(* Logix 5000 project; controller ControlLogix 1756-L63 rev 16.7; software revision 16.03 *)

TASK MainTask (continuous, watchdog 500 ms) : MainProgram

MODULES
   Local : 1756-L63 (ICP 0, rev 16.7)
      MCM : vendor 1 type 0 code 15 (ICP 1, rev 1.1, Output RPI 5 ms)   // ProSoft Technology Modbus communication module for the Control logix platform
END_MODULES

TYPE _CmdControl :
STRUCT
   TriggerCmdCntrl : BOOL;
   NumberOfCommands : INT;
   PortNumber : INT;
   CommandIndex : INT[6];
   CmdsAddedToQueue : INT;
   CmdControlBlockID : INT;
   CmdCntrlPending : BOOL;
END_STRUCT
END_TYPE

TYPE _CoilArray :
STRUCT
   Boolean : BOOL[416];
END_STRUCT
END_TYPE

TYPE _EventCmd :
STRUCT
   EventCmdTrigger : BOOL;
   EventCmdPending : BOOL;
   PortNumber : INT;
   SlaveAddress : INT;
   InternalDBAddress : INT;
   PointCount : INT;
   SwapCode : INT;
   ModbusFunctionCode : INT;
   DeviceDBAddress : INT;
   EventCmdStatusReturned : INT;
   EventBlockID : INT;
END_STRUCT
END_TYPE

TYPE _Passthru :
STRUCT
   MBOffset : INT;
   MBOffsetBit : INT;
   MBMsgLen : INT;
   MBMsg : SINT[500];
   MBControl1 : CONTROL;
   MBControl2 : CONTROL;
   MBScratch : INT[3];
   MBCoil : _CoilArray;
END_STRUCT
END_TYPE

TYPE _SlavePollStatus :
STRUCT
   Port1Slave0Read : BOOL;
   Port1Slave128Read : BOOL;
   Port2Slave0Read : BOOL;
   Port2Slave128Read : BOOL;
   P1Slaves : INT[256];
   P2Slaves : INT[256];
END_STRUCT
END_TYPE

TYPE _Util :
STRUCT
   CmdControl : _CmdControl;
   EventCmd : _EventCmd;
   SlavePollStat : _SlavePollStatus;
   Passthru : _Passthru;
END_STRUCT
END_TYPE

TYPE MCMBlkStat :
STRUCT
   Read : INT;
   Write : INT;
   Parse : INT;
   Event : INT;
   Cmd : INT;
   Err : INT;
END_STRUCT
END_TYPE

TYPE MCMCmd :
STRUCT
   Enable : INT;
   IntAddress : INT;
   PollInt : INT;
   Count : INT;
   Swap : INT;
   Node : INT;
   Func : INT;
   DevAddress : INT;
END_STRUCT
END_TYPE

TYPE MCMCONFIG :
STRUCT
   ModDef : MCMModule;
   Port1 : MCMPort;
   Port2 : MCMPort;
   Port1MasterCmd : MCMCmd[100];
   Port2MasterCmd : MCMCmd[100];
END_STRUCT
END_TYPE

TYPE MCMCONTROL :
STRUCT
   WarmBoot : BOOL;
   ColdBoot : BOOL;
   BPLastRead : INT;
   BPLastWrite : INT;
   BlockIndex : INT;
   ReadDataSize : DINT;
   MaxReadBlock : DINT;
   WriteDataSize : DINT;
   MaxWriteBlock : DINT;
END_STRUCT
END_TYPE

TYPE MCMDATA :
STRUCT
   ReadData : INT[600];
   WriteData : INT[600];
END_STRUCT
END_TYPE

TYPE MCMModule :
STRUCT
   WriteStartReg : INT;
   WriteRegCnt : INT;
   ReadStartReg : INT;
   ReadRegCnt : INT;
   BPFail : INT;
   ErrStatPtr : INT;
END_STRUCT
END_TYPE

TYPE MCMModuleDef :
STRUCT
   CONFIG : MCMCONFIG;
   DATA : MCMDATA;
   STATUS : MCMSTATUS;
   CONTROL : MCMCONTROL;
   _UTIL : _Util;
END_STRUCT
END_TYPE

TYPE MCMPort :
STRUCT
   Enabled : INT;
   Type : INT;
   FloatFlag : INT;
   FloatStart : INT;
   FloatOffset : INT;
   Protocol : INT;
   Baudrate : INT;
   Parity : INT;
   DataBits : INT;
   StopBits : INT;
   RTSOn : INT;
   RTSOff : INT;
   MinResp : INT;
   UseCTS : INT;
   SlaveID : INT;
   BitInOffset : INT;
   WordInOffset : INT;
   OutOffset : INT;
   HoldOffset : INT;
   CmdCount : INT;
   MinCmdDelay : INT;
   CmdErrPtr : INT;
   RespTO : INT;
   RetryCount : INT;
   ErrorDelayCntr : INT;
   Reserved : INT;
   InterCharacterDelay : INT;
   Fcn99Offset : INT;
END_STRUCT
END_TYPE

TYPE MCMPortErrors :
STRUCT
   CmdReq : INT;
   CmdResp : INT;
   CmdErr : INT;
   Requests : INT;
   Responses : INT;
   ErrSent : INT;
   ErrRec : INT;
END_STRUCT
END_TYPE

TYPE MCMSTATUS :
STRUCT
   PassCnt : INT;
   Product : INT[2];
   Rev : INT[2];
   OP : INT[2];
   Run : INT[2];
   Prt1Errs : MCMPortErrors;
   Prt2Errs : MCMPortErrors;
   Blk : MCMBlkStat;
   Port1LastErr : INT;
   Port1PreviousErr : INT;
   Port2LastErr : INT;
   Port2PreviousErr : INT;
END_STRUCT
END_TYPE

ADD_ON_INSTRUCTION PSMCM   (* revision 2.2, ExecutePrescan *)
// Revision note:
// Added viewing capability for the Add_On Instruction
VAR_IN_OUT
   Local_C : SINT[400]; {required}
   Local_Input : INT[250]; {required}
   Local_Output : INT[248]; {required}
   MCM : MCMModuleDef; {required}
END_VAR
VAR
   MJFAULTS : DINT[12];
END_VAR

ROUTINE Logic   (* ladder *)
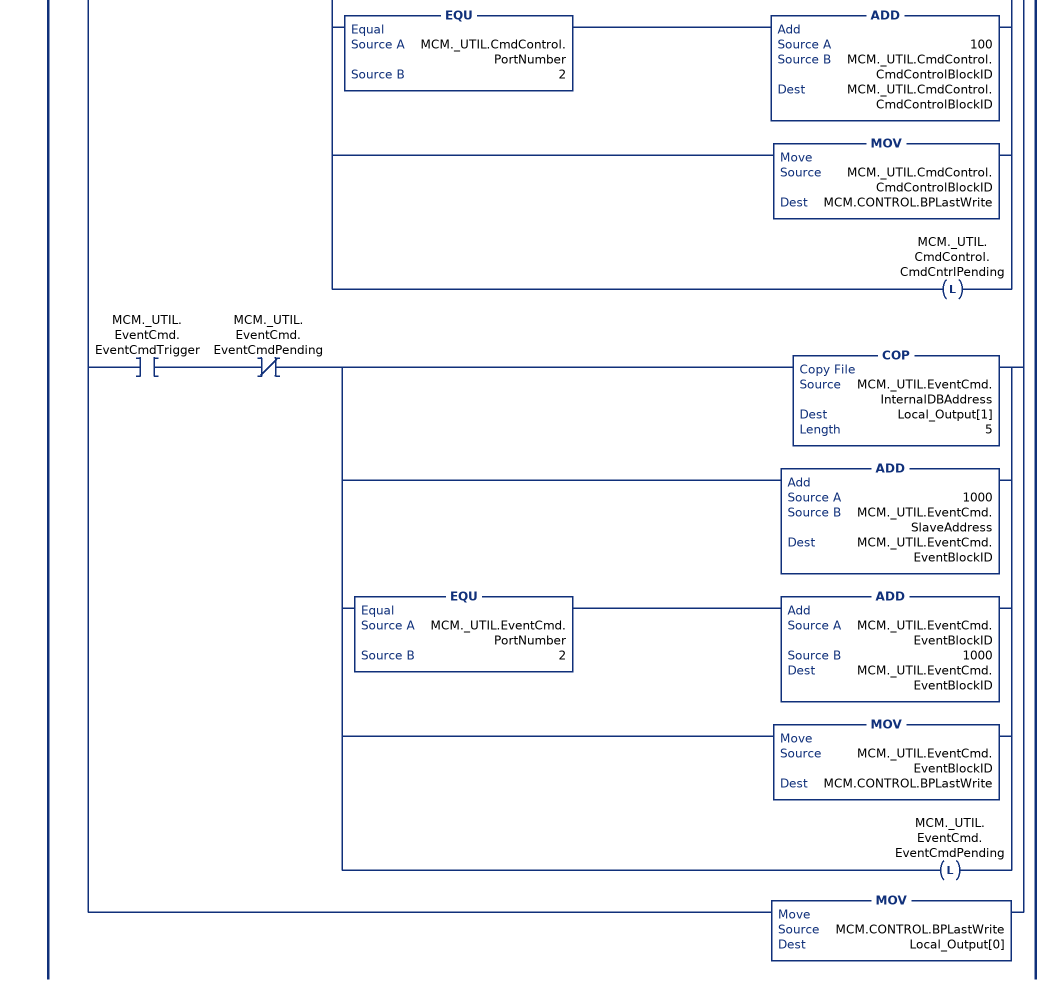
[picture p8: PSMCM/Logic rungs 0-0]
   0: NEQ(Local_Input[249],MCM.CONTROL.BPLastRead)[MOV(Local_Input[249],MCM.CONTROL.BPLastRead) ,[EQU(-1,MCM.CONTROL.BPLastRead) ,EQU(0,MCM.CONTROL.BPLastRead) ] [COP(Local_Input[202],MCM.STATUS.PassCnt,1) ,COP(Local_Input[203],MCM.STATUS.Product[0],8) ,COP(Local_Input[211],MCM.STATUS.Prt1Errs.CmdReq,7) ,COP(Local_Input[218],MCM.STATUS.Prt2Errs.CmdReq,7) ,COP(Local_Input[225],MCM.STATUS.Blk.Read,6) ,COP(Local_Input[231],MCM.STATUS.Port1LastErr,4) ] ,LIM(1,MCM.CONTROL.BPLastRead,MCM.CONTROL.MaxReadBlock) [CPT(MCM.CONTROL.BlockIndex,(MCM.CONTROL.BPLastRead-1)*200) ,COP(Local_Input[2],MCM.DATA.ReadData[MCM.CONTROL.BlockIndex],200) ,COP(Local_Input[202],MCM.STATUS.PassCnt,1) ,COP(Local_Input[203],MCM.STATUS.Product[0],8) ,COP(Local_Input[211],MCM.STATUS.Prt1Errs.CmdReq,7) ,COP(Local_Input[218],MCM.STATUS.Prt2Errs.CmdReq,7) ,COP(Local_Input[225],MCM.STATUS.Blk.Read,6) ,COP(Local_Input[231],MCM.STATUS.Port1LastErr,4) ] ,EQU(9996,MCM.CONTROL.BPLastRead) [MOV(Local_Input[2],MCM._UTIL.Passthru.MBMsgLen) ,COP(Local_Input[4],MCM._UTIL.Passthru.MBMsg[0],MCM._UTIL.Passthru.MBMsgLen) ] ,LIM(9956,MCM.CONTROL.BPLastRead,9957) [MOV(Local_Input[3],MCM._UTIL.Passthru.MBOffset) ,COP(Local_Input[4],MCM.DATA.WriteData[MCM._UTIL.Passthru.MBOffset],Local_Input[2]) ] ,EQU(9958,MCM.CONTROL.BPLastRead) LES(Local_Input[3],416) [MOV(Local_Input[3],MCM._UTIL.Passthru.MBOffsetBit) ,MOV(Local_Input[4],MCM._UTIL.Passthru.MBScratch[2]) ,COP(MCM.DATA.WriteData[0],MCM._UTIL.Passthru.MBCoil,1) ,NEQ(MCM._UTIL.Passthru.MBScratch[2],0) OTL(MCM._UTIL.Passthru.MBCoil.Boolean[MCM._UTIL.Passthru.MBOffsetBit]) ,EQU(MCM._UTIL.Passthru.MBScratch[2],0) OTU(MCM._UTIL.Passthru.MBCoil.Boolean[MCM._UTIL.Passthru.MBOffsetBit]) ,COP(MCM._UTIL.Passthru.MBCoil,MCM.DATA.WriteData[0],26) ] ,EQU(9959,MCM.CONTROL.BPLastRead) [MOV(Local_Input[3],MCM._UTIL.Passthru.MBOffset) ,MOV(Local_Input[2],MCM._UTIL.Passthru.MBControl1.LEN) ,MOV(Local_Input[2],MCM._UTIL.Passthru.MBControl2.LEN) ,FAL(MCM._UTIL.Passthru.MBControl1,?,?,ALL,MCM.DATA.WriteData[MCM._UTIL.Passthru.MBOffset+MCM._UTIL.Passthru.MBControl1.POS],MCM.DATA.WriteData[MCM._UTIL.Passthru.MBOffset+MCM._UTIL.Passthru.MBControl1.POS] AND(NOT Local_Input[54+MCM._UTIL.Passthru.MBControl1.POS])) ,FAL(MCM._UTIL.Passthru.MBControl2,?,?,ALL,MCM.DATA.WriteData[MCM._UTIL.Passthru.MBOffset+MCM._UTIL.Passthru.MBControl2.POS],MCM.DATA.WriteData[MCM._UTIL.Passthru.MBOffset+MCM._UTIL.Passthru.MBControl2.POS] OR(Local_Input[54+MCM._UTIL.Passthru.MBControl2.POS] AND Local_Input[4+MCM._UTIL.Passthru.MBControl2.POS])) ,RES(MCM._UTIL.Passthru.MBControl1) ,RES(MCM._UTIL.Passthru.MBControl2) ] ,LIM(3002,MCM.CONTROL.BPLastRead,3003) [CPT(MCM.CONTROL.BlockIndex,(MCM.CONTROL.BPLastRead-3002)*128) ,COP(Local_Input[2],MCM._UTIL.SlavePollStat.P1Slaves[MCM.CONTROL.BlockIndex],128) ] ,LIM(3102,MCM.CONTROL.BPLastRead,3103) [CPT(MCM.CONTROL.BlockIndex,(MCM.CONTROL.BPLastRead-3102)*128) ,COP(Local_Input[2],MCM._UTIL.SlavePollStat.P2Slaves[MCM.CONTROL.BlockIndex],128) ] ,[LIM(5001,MCM.CONTROL.BPLastRead,5006) ,LIM(5101,MCM.CONTROL.BPLastRead,5106) ] [MOV(Local_Input[2],MCM._UTIL.CmdControl.CmdsAddedToQueue) ,OTU(MCM._UTIL.CmdControl.CmdCntrlPending) ,OTU(MCM._UTIL.CmdControl.TriggerCmdCntrl) ] ,[LIM(1000,MCM.CONTROL.BPLastRead,1255) ,LIM(2000,MCM.CONTROL.BPLastRead,2255) ] [MOV(Local_Input[2],MCM._UTIL.EventCmd.EventCmdStatusReturned) ,OTU(MCM._UTIL.EventCmd.EventCmdPending) ,OTU(MCM._UTIL.EventCmd.EventCmdTrigger) ] ,EQU(-9000,MCM.CONTROL.BPLastRead) [COP(Local_Input[2],MCM.CONFIG.ModDef.WriteStartReg,6) ,COP(Local_Input[8],MCM.CONFIG.Port1.Enabled,25) ,COP(Local_Input[33],MCM.CONFIG.Port2.Enabled,25) ,COP(Local_Input[58],MCM.CONFIG.Port1.Reserved,3) ,COP(Local_Input[61],MCM.CONFIG.Port2.Reserved,3) ,MOV(MCM.CONTROL.BPLastRead,Local_Output[0]) ] ,LIM(-6003,MCM.CONTROL.BPLastRead,-6000) [CPT(MCM.CONTROL.BPLastWrite,(-MCM.CONTROL.BPLastRead-6000)*25) ,COP(Local_Input[2],MCM.CONFIG.Port1MasterCmd[MCM.CONTROL.BPLastWrite].Enable,200) ,MOV(MCM.CONTROL.BPLastRead,Local_Output[0]) ] ,LIM(-6103,MCM.CONTROL.BPLastRead,-6100) [CPT(MCM.CONTROL.BPLastWrite,(-MCM.CONTROL.BPLastRead-6100)*25) ,COP(Local_Input[2],MCM.CONFIG.Port2MasterCmd[MCM.CONTROL.BPLastWrite].Enable,200) ,MOV(MCM.CONTROL.BPLastRead,Local_Output[0]) ] ,MOV(Local_Input[1],MCM.CONTROL.BPLastWrite) ,XIC(MCM.CONTROL.WarmBoot) [MOV(9998,MCM.CONTROL.BPLastWrite) ,OTU(MCM.CONTROL.WarmBoot) ] ,XIC(MCM.CONTROL.ColdBoot) [MOV(9999,MCM.CONTROL.BPLastWrite) ,OTU(MCM.CONTROL.ColdBoot) ] ,LIM(1,MCM.CONTROL.BPLastWrite,MCM.CONTROL.MaxWriteBlock) [CPT(MCM.CONTROL.BlockIndex,(MCM.CONTROL.BPLastWrite-1)*200) ,COP(MCM.DATA.WriteData[MCM.CONTROL.BlockIndex],Local_Output[1],200) ] ,EQU(9000,MCM.CONTROL.BPLastWrite) [COP(MCM.CONFIG.ModDef.WriteStartReg,Local_Output[1],6) ,COP(MCM.CONFIG.Port1.Enabled,Local_Output[7],25) ,COP(MCM.CONFIG.Port2.Enabled,Local_Output[32],25) ,COP(MCM.CONFIG.Port1.Reserved,Local_Output[57],3) ,COP(MCM.CONFIG.Port2.Reserved,Local_Output[60],3) ] ,LIM(6000,MCM.CONTROL.BPLastWrite,6003) [CPT(MCM.CONTROL.BlockIndex,(MCM.CONTROL.BPLastWrite-6000)*25) ,COP(MCM.CONFIG.Port1MasterCmd[MCM.CONTROL.BlockIndex].Enable,Local_Output[1],200) ] ,LIM(6100,MCM.CONTROL.BPLastWrite,6103) [CPT(MCM.CONTROL.BlockIndex,(MCM.CONTROL.BPLastWrite-6100)*25) ,COP(MCM.CONFIG.Port2MasterCmd[MCM.CONTROL.BlockIndex].Enable,Local_Output[1],200) ] ,XIC(MCM._UTIL.SlavePollStat.Port1Slave0Read) [MOV(3002,MCM.CONTROL.BPLastWrite) ,OTU(MCM._UTIL.SlavePollStat.Port1Slave0Read) ] ,XIC(MCM._UTIL.SlavePollStat.Port1Slave128Read) [MOV(3003,MCM.CONTROL.BPLastWrite) ,OTU(MCM._UTIL.SlavePollStat.Port1Slave128Read) ] ,XIC(MCM._UTIL.SlavePollStat.Port2Slave0Read) [MOV(3102,MCM.CONTROL.BPLastWrite) ,OTU(MCM._UTIL.SlavePollStat.Port2Slave0Read) ] ,XIC(MCM._UTIL.SlavePollStat.Port2Slave128Read) [MOV(3103,MCM.CONTROL.BPLastWrite) ,OTU(MCM._UTIL.SlavePollStat.Port2Slave128Read) ] ,XIC(MCM._UTIL.CmdControl.TriggerCmdCntrl) XIO(MCM._UTIL.CmdControl.CmdCntrlPending) [COP(MCM._UTIL.CmdControl.CommandIndex[0],Local_Output[1],6) ,ADD(5000,MCM._UTIL.CmdControl.NumberOfCommands,MCM._UTIL.CmdControl.CmdControlBlockID) ,EQU(MCM._UTIL.CmdControl.PortNumber,2) ADD(100,MCM._UTIL.CmdControl.CmdControlBlockID,MCM._UTIL.CmdControl.CmdControlBlockID) ,MOV(MCM._UTIL.CmdControl.CmdControlBlockID,MCM.CONTROL.BPLastWrite) ,OTL(MCM._UTIL.CmdControl.CmdCntrlPending) ] ,XIC(MCM._UTIL.EventCmd.EventCmdTrigger) XIO(MCM._UTIL.EventCmd.EventCmdPending) [COP(MCM._UTIL.EventCmd.InternalDBAddress,Local_Output[1],5) ,ADD(1000,MCM._UTIL.EventCmd.SlaveAddress,MCM._UTIL.EventCmd.EventBlockID) ,EQU(MCM._UTIL.EventCmd.PortNumber,2) ADD(MCM._UTIL.EventCmd.EventBlockID,1000,MCM._UTIL.EventCmd.EventBlockID) ,MOV(MCM._UTIL.EventCmd.EventBlockID,MCM.CONTROL.BPLastWrite) ,OTL(MCM._UTIL.EventCmd.EventCmdPending) ] ,MOV(MCM.CONTROL.BPLastWrite,Local_Output[0]) ];
END_ROUTINE

ROUTINE Prescan   (* ladder *)
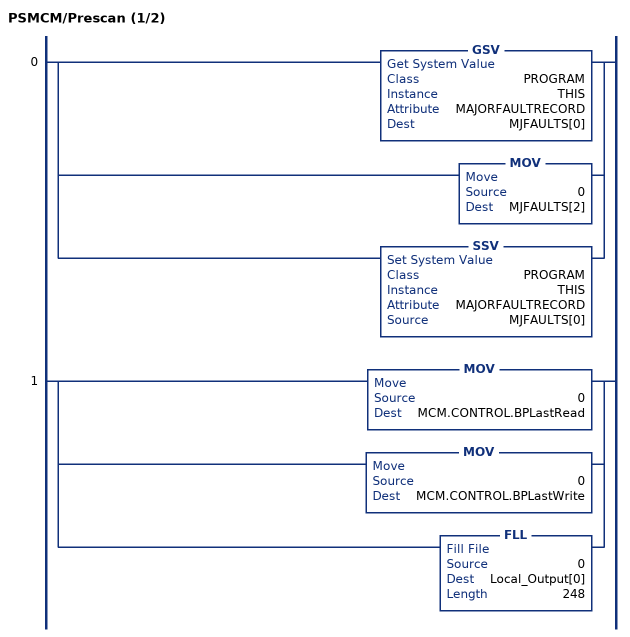
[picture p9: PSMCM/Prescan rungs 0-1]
   0: [GSV(PROGRAM,THIS,MAJORFAULTRECORD,MJFAULTS[0]) ,MOV(0,MJFAULTS[2]) ,SSV(PROGRAM,THIS,MAJORFAULTRECORD,MJFAULTS[0]) ];
   1: [MOV(0,MCM.CONTROL.BPLastRead) ,MOV(0,MCM.CONTROL.BPLastWrite) ,FLL(0,Local_Output[0],248) ];
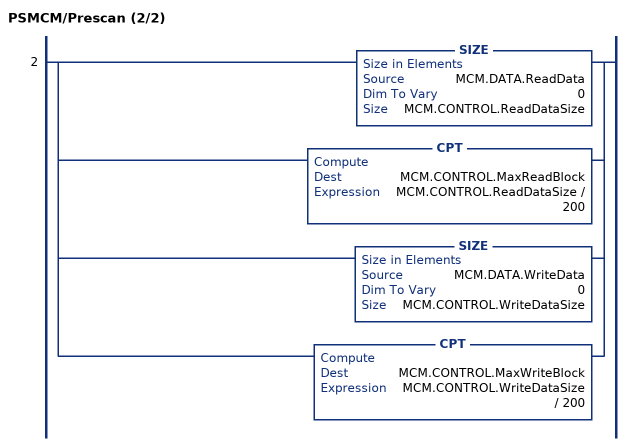
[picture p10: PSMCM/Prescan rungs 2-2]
   2: [SIZE(MCM.DATA.ReadData,0,MCM.CONTROL.ReadDataSize) ,CPT(MCM.CONTROL.MaxReadBlock,MCM.CONTROL.ReadDataSize / 200) ,SIZE(MCM.DATA.WriteData,0,MCM.CONTROL.WriteDataSize) ,CPT(MCM.CONTROL.MaxWriteBlock,MCM.CONTROL.WriteDataSize / 200) ];
END_ROUTINE
END_ADD_ON_INSTRUCTION

VAR_GLOBAL   (* controller tags *)
   MCM : MCMModuleDef;
   PSMCM : PSMCM;
END_VAR

PROGRAM MainProgram   (* main routine MainRoutine *)

ROUTINE MainRoutine   (* ladder *)
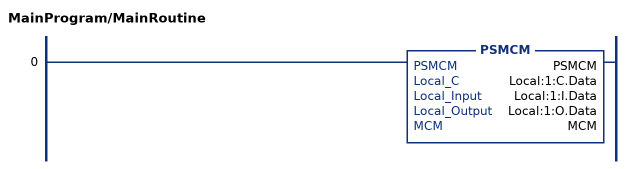
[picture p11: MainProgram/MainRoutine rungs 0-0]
   0: PSMCM(PSMCM,Local:1:C.Data,Local:1:I.Data,Local:1:O.Data,MCM);
END_ROUTINE
END_PROGRAM
